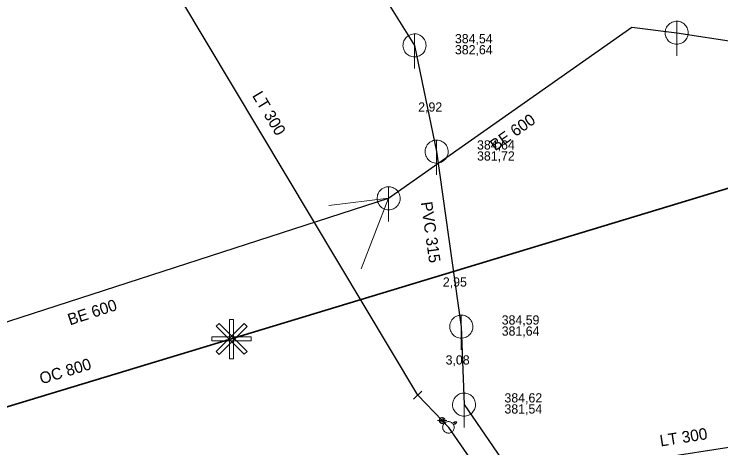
# Model space of a CAD drawing. Extents: x -809028 to -807737, y -990545 to -989489.
# Drawn here: x -808089.3 to -808027.9, y -989998.8 to -989961.2 of the extents above; entities that cross this region are included whole.
import ezdxf

# ---------------------------------------------------------------- set-up
doc = ezdxf.new("R2010")
doc.units = 0
doc.header["$LTSCALE"] = 0.32
for name, color, linetype, lineweight in [('1', 7, 'Continuous', 13), ('11', 7, 'Continuous', 13), ('12', 7, 'Continuous', 13), ('14', 7, 'Continuous', 25), ('17', 7, 'Continuous', 25), ('22', 7, 'Continuous', 13), ('23', 7, 'Continuous', 13), ('34', 7, 'Continuous', 13), ('9', 7, 'Continuous', 13)]:
    doc.layers.add(name, color=color, linetype=linetype, lineweight=lineweight)

msp = doc.modelspace()

# ---------------------------------------------------------------- linework, layer by layer
at = {"layer": '11'}
for p in [(-808061.958, -989977.796), (-808059.125, -989983.296)]:
    msp.add_line(p, (-808056.754, -989977.17), dxfattribs=at)
at = {"layer": '12'}
for points in [[(-808070.557, -989987.672), (-808070.206, -989987.672), (-808070.206, -989991.107), (-808070.557, -989991.107)], [(-808069.291, -989988.036), (-808069.043, -989988.284), (-808071.472, -989990.713), (-808071.718, -989990.465)], [(-808071.71, -989988.275), (-808071.463, -989988.027), (-808069.034, -989990.456), (-808069.281, -989990.704)], [(-808068.673, -989989.181), (-808068.673, -989989.531), (-808072.108, -989989.531), (-808072.108, -989989.181)]]:
    msp.add_lwpolyline(points, close=True, dxfattribs=at)
at = {"layer": '14'}
for p, q in [((-808068.949, -989940.649), (-808054.51, -989963.899)), ((-808031.76, -989962.8), (-808009.03, -989966.258)), ((-808054.51, -989963.899), (-808052.59, -989973.12)), ((-808052.59, -989973.12), (-808050.449, -989988.309)), ((-808107.581, -989993.61), (-808056.754, -989977.17)), ((-808050.449, -989988.309), (-808050.21, -989995.07)), ((-808050.21, -989995.07), (-808041.129, -990008.23))]:
    msp.add_line(p, q, dxfattribs=at)
at = {"layer": '14', "lineweight": 13}
for p, q in [((-808052.113, -989996.453), (-808054.229, -989994.256)), ((-808051.536, -989997.052), (-808052.113, -989996.453))]:
    msp.add_line(p, q, dxfattribs=at)
at = {"layer": '14'}
msp.add_lwpolyline([(-808056.754, -989977.17), (-808035.64, -989962.329), (-808031.76, -989962.8)], dxfattribs=at)
at = {"layer": '17'}
msp.add_line((-808054.229, -989994.256), (-808081.64, -989948.42), dxfattribs=at)
at = {"layer": '17', "lineweight": 35}
msp.add_lwpolyline([(-808175.378, -990021.169), (-807992.059, -989965.616), (-807931.655, -989894.969), (-807887.769, -989859.528)], dxfattribs=at)
at = {"layer": '17'}
msp.add_lwpolyline([(-808011.965, -989996.426), (-808048.094, -990002.026), (-808051.536, -989997.052)], dxfattribs=at)
at = {"layer": '22'}
for p, q in [((-808031.76, -989964.8), (-808031.759, -989961.8)), ((-808054.51, -989965.899), (-808054.509, -989962.899)), ((-808052.59, -989975.12), (-808052.589, -989972.12)), ((-808056.754, -989979.17), (-808056.753, -989976.17)), ((-808050.449, -989990.309), (-808050.448, -989987.309)), ((-808050.21, -989997.07), (-808050.209, -989994.07))]:
    msp.add_line(p, q, dxfattribs=at)
for points in [[(-808030.76, -989962.8), (-808030.765, -989962.691), (-808030.783, -989962.583), (-808030.813, -989962.477), (-808030.853, -989962.376), (-808030.905, -989962.279), (-808030.967, -989962.189), (-808031.039, -989962.106), (-808031.119, -989962.032), (-808031.207, -989961.966), (-808031.301, -989961.911), (-808031.401, -989961.866), (-808031.506, -989961.833), (-808031.613, -989961.811), (-808031.722, -989961.801), (-808031.832, -989961.803), (-808031.94, -989961.817), (-808032.047, -989961.842), (-808032.15, -989961.879), (-808032.248, -989961.928), (-808032.34, -989961.986), (-808032.426, -989962.055), (-808032.503, -989962.132), (-808032.572, -989962.218), (-808032.631, -989962.31), (-808032.679, -989962.408), (-808032.716, -989962.511), (-808032.742, -989962.618), (-808032.756, -989962.726), (-808032.759, -989962.836), (-808032.749, -989962.945), (-808032.728, -989963.052), (-808032.694, -989963.156), (-808032.65, -989963.256), (-808032.595, -989963.351), (-808032.529, -989963.439), (-808032.455, -989963.519), (-808032.372, -989963.591), (-808032.282, -989963.653), (-808032.186, -989963.705), (-808032.084, -989963.746), (-808031.979, -989963.776), (-808031.871, -989963.794), (-808031.761, -989963.8), (-808031.652, -989963.794), (-808031.544, -989963.776), (-808031.439, -989963.747), (-808031.337, -989963.706), (-808031.24, -989963.654), (-808031.15, -989963.592), (-808031.067, -989963.521), (-808030.992, -989963.441), (-808030.927, -989963.353), (-808030.871, -989963.259), (-808030.827, -989963.159), (-808030.793, -989963.055), (-808030.771, -989962.947), (-808030.761, -989962.838)], [(-808053.51, -989963.899), (-808053.515, -989963.79), (-808053.533, -989963.682), (-808053.563, -989963.576), (-808053.603, -989963.475), (-808053.655, -989963.378), (-808053.717, -989963.288), (-808053.789, -989963.205), (-808053.869, -989963.131), (-808053.957, -989963.065), (-808054.051, -989963.01), (-808054.151, -989962.965), (-808054.256, -989962.932), (-808054.363, -989962.91), (-808054.472, -989962.9), (-808054.582, -989962.902), (-808054.69, -989962.916), (-808054.797, -989962.941), (-808054.9, -989962.978), (-808054.998, -989963.027), (-808055.09, -989963.085), (-808055.176, -989963.154), (-808055.253, -989963.231), (-808055.322, -989963.317), (-808055.381, -989963.409), (-808055.429, -989963.507), (-808055.466, -989963.61), (-808055.492, -989963.717), (-808055.506, -989963.825), (-808055.509, -989963.935), (-808055.499, -989964.044), (-808055.478, -989964.151), (-808055.444, -989964.255), (-808055.4, -989964.355), (-808055.345, -989964.45), (-808055.279, -989964.538), (-808055.205, -989964.618), (-808055.122, -989964.69), (-808055.032, -989964.752), (-808054.936, -989964.804), (-808054.834, -989964.845), (-808054.729, -989964.875), (-808054.621, -989964.893), (-808054.511, -989964.899), (-808054.402, -989964.893), (-808054.294, -989964.875), (-808054.189, -989964.846), (-808054.087, -989964.805), (-808053.99, -989964.753), (-808053.9, -989964.691), (-808053.817, -989964.62), (-808053.742, -989964.54), (-808053.677, -989964.452), (-808053.621, -989964.358), (-808053.577, -989964.258), (-808053.543, -989964.154), (-808053.521, -989964.046), (-808053.511, -989963.937)], [(-808051.59, -989973.12), (-808051.595, -989973.011), (-808051.613, -989972.903), (-808051.643, -989972.797), (-808051.683, -989972.696), (-808051.735, -989972.599), (-808051.797, -989972.509), (-808051.869, -989972.426), (-808051.949, -989972.352), (-808052.037, -989972.286), (-808052.131, -989972.231), (-808052.231, -989972.186), (-808052.336, -989972.153), (-808052.443, -989972.131), (-808052.552, -989972.121), (-808052.662, -989972.123), (-808052.77, -989972.137), (-808052.877, -989972.162), (-808052.98, -989972.199), (-808053.078, -989972.248), (-808053.17, -989972.306), (-808053.256, -989972.375), (-808053.333, -989972.452), (-808053.402, -989972.538), (-808053.461, -989972.63), (-808053.509, -989972.728), (-808053.546, -989972.831), (-808053.572, -989972.938), (-808053.586, -989973.046), (-808053.589, -989973.156), (-808053.579, -989973.265), (-808053.558, -989973.372), (-808053.524, -989973.476), (-808053.48, -989973.576), (-808053.425, -989973.671), (-808053.359, -989973.759), (-808053.285, -989973.839), (-808053.202, -989973.911), (-808053.112, -989973.973), (-808053.016, -989974.025), (-808052.914, -989974.066), (-808052.809, -989974.096), (-808052.701, -989974.114), (-808052.591, -989974.12), (-808052.482, -989974.114), (-808052.374, -989974.096), (-808052.269, -989974.067), (-808052.167, -989974.026), (-808052.07, -989973.974), (-808051.98, -989973.912), (-808051.897, -989973.841), (-808051.822, -989973.761), (-808051.757, -989973.673), (-808051.701, -989973.579), (-808051.657, -989973.479), (-808051.623, -989973.375), (-808051.601, -989973.267), (-808051.591, -989973.158)], [(-808055.754, -989977.17), (-808055.759, -989977.061), (-808055.777, -989976.953), (-808055.807, -989976.847), (-808055.847, -989976.746), (-808055.899, -989976.649), (-808055.961, -989976.559), (-808056.033, -989976.476), (-808056.113, -989976.402), (-808056.201, -989976.336), (-808056.295, -989976.281), (-808056.395, -989976.236), (-808056.5, -989976.203), (-808056.607, -989976.181), (-808056.716, -989976.171), (-808056.826, -989976.173), (-808056.934, -989976.187), (-808057.041, -989976.212), (-808057.144, -989976.249), (-808057.242, -989976.298), (-808057.334, -989976.356), (-808057.42, -989976.425), (-808057.497, -989976.502), (-808057.566, -989976.588), (-808057.625, -989976.68), (-808057.673, -989976.778), (-808057.71, -989976.881), (-808057.736, -989976.988), (-808057.75, -989977.096), (-808057.753, -989977.206), (-808057.743, -989977.315), (-808057.722, -989977.422), (-808057.688, -989977.526), (-808057.644, -989977.626), (-808057.589, -989977.721), (-808057.523, -989977.809), (-808057.449, -989977.889), (-808057.366, -989977.961), (-808057.276, -989978.023), (-808057.18, -989978.075), (-808057.078, -989978.116), (-808056.973, -989978.146), (-808056.865, -989978.164), (-808056.755, -989978.17), (-808056.646, -989978.164), (-808056.538, -989978.146), (-808056.433, -989978.117), (-808056.331, -989978.076), (-808056.234, -989978.024), (-808056.144, -989977.962), (-808056.061, -989977.891), (-808055.986, -989977.811), (-808055.921, -989977.723), (-808055.865, -989977.629), (-808055.821, -989977.529), (-808055.787, -989977.425), (-808055.765, -989977.317), (-808055.755, -989977.208)], [(-808049.449, -989988.309), (-808049.454, -989988.2), (-808049.472, -989988.092), (-808049.502, -989987.986), (-808049.542, -989987.885), (-808049.594, -989987.788), (-808049.656, -989987.698), (-808049.728, -989987.615), (-808049.808, -989987.541), (-808049.896, -989987.475), (-808049.99, -989987.42), (-808050.09, -989987.375), (-808050.195, -989987.342), (-808050.302, -989987.32), (-808050.411, -989987.31), (-808050.521, -989987.312), (-808050.629, -989987.326), (-808050.736, -989987.351), (-808050.839, -989987.388), (-808050.937, -989987.437), (-808051.029, -989987.495), (-808051.115, -989987.564), (-808051.192, -989987.641), (-808051.261, -989987.727), (-808051.32, -989987.819), (-808051.368, -989987.917), (-808051.405, -989988.02), (-808051.431, -989988.127), (-808051.445, -989988.235), (-808051.448, -989988.345), (-808051.438, -989988.454), (-808051.417, -989988.561), (-808051.383, -989988.665), (-808051.339, -989988.765), (-808051.284, -989988.86), (-808051.218, -989988.948), (-808051.144, -989989.028), (-808051.061, -989989.1), (-808050.971, -989989.162), (-808050.875, -989989.214), (-808050.773, -989989.255), (-808050.668, -989989.285), (-808050.56, -989989.303), (-808050.45, -989989.309), (-808050.341, -989989.303), (-808050.233, -989989.285), (-808050.128, -989989.256), (-808050.026, -989989.215), (-808049.929, -989989.163), (-808049.839, -989989.101), (-808049.756, -989989.03), (-808049.681, -989988.95), (-808049.616, -989988.862), (-808049.56, -989988.768), (-808049.516, -989988.668), (-808049.482, -989988.564), (-808049.46, -989988.456), (-808049.45, -989988.347)], [(-808049.21, -989995.07), (-808049.215, -989994.961), (-808049.233, -989994.853), (-808049.263, -989994.747), (-808049.303, -989994.646), (-808049.355, -989994.549), (-808049.417, -989994.459), (-808049.489, -989994.376), (-808049.569, -989994.302), (-808049.657, -989994.236), (-808049.751, -989994.181), (-808049.851, -989994.136), (-808049.956, -989994.103), (-808050.063, -989994.081), (-808050.172, -989994.071), (-808050.282, -989994.073), (-808050.39, -989994.087), (-808050.497, -989994.112), (-808050.6, -989994.149), (-808050.698, -989994.198), (-808050.79, -989994.256), (-808050.876, -989994.325), (-808050.953, -989994.402), (-808051.022, -989994.488), (-808051.081, -989994.58), (-808051.129, -989994.678), (-808051.166, -989994.781), (-808051.192, -989994.888), (-808051.206, -989994.996), (-808051.209, -989995.106), (-808051.199, -989995.215), (-808051.178, -989995.322), (-808051.144, -989995.426), (-808051.1, -989995.526), (-808051.045, -989995.621), (-808050.979, -989995.709), (-808050.905, -989995.789), (-808050.822, -989995.861), (-808050.732, -989995.923), (-808050.636, -989995.975), (-808050.534, -989996.016), (-808050.429, -989996.046), (-808050.321, -989996.064), (-808050.211, -989996.07), (-808050.102, -989996.064), (-808049.994, -989996.046), (-808049.889, -989996.017), (-808049.787, -989995.976), (-808049.69, -989995.924), (-808049.6, -989995.862), (-808049.517, -989995.791), (-808049.442, -989995.711), (-808049.377, -989995.623), (-808049.321, -989995.529), (-808049.277, -989995.429), (-808049.243, -989995.325), (-808049.221, -989995.217), (-808049.211, -989995.108)]]:
    msp.add_lwpolyline(points, close=True, dxfattribs=at)
at = {"layer": '23'}
msp.add_line((-808050.954, -989996.754), (-808051.066, -989996.592), dxfattribs=at)
for points in [[(-808051.278, -989997.454), (-808051.237, -989997.421), (-808051.199, -989997.384), (-808051.167, -989997.344), (-808051.138, -989997.3), (-808051.113, -989997.254), (-808051.094, -989997.205), (-808051.08, -989997.155), (-808051.072, -989997.104), (-808051.068, -989997.051), (-808051.07, -989996.999), (-808051.077, -989996.947), (-808051.091, -989996.896), (-808051.108, -989996.847), (-808051.132, -989996.801), (-808051.159, -989996.757), (-808051.193, -989996.715), (-808051.228, -989996.678), (-808051.27, -989996.644), (-808051.311, -989996.615), (-808051.358, -989996.59), (-808051.408, -989996.572), (-808051.458, -989996.558), (-808051.511, -989996.549), (-808051.562, -989996.545), (-808051.614, -989996.547), (-808051.666, -989996.556), (-808051.716, -989996.568), (-808051.765, -989996.587), (-808051.812, -989996.611), (-808051.857, -989996.638), (-808051.898, -989996.67), (-808051.935, -989996.707), (-808051.969, -989996.747), (-808051.998, -989996.79), (-808052.021, -989996.836), (-808052.04, -989996.885), (-808052.055, -989996.936), (-808052.064, -989996.988), (-808052.067, -989997.04)], [(-808051.27, -989996.644), (-808051.311, -989996.615), (-808051.358, -989996.59), (-808051.408, -989996.572), (-808051.458, -989996.558), (-808051.511, -989996.549), (-808051.562, -989996.545), (-808051.614, -989996.547), (-808051.666, -989996.556), (-808051.716, -989996.568), (-808051.765, -989996.587), (-808051.812, -989996.611), (-808051.857, -989996.638), (-808051.898, -989996.67), (-808051.935, -989996.707), (-808051.969, -989996.747), (-808051.998, -989996.79), (-808052.021, -989996.836), (-808052.04, -989996.885), (-808052.055, -989996.936), (-808052.064, -989996.988), (-808052.067, -989997.04), (-808052.066, -989997.091), (-808052.057, -989997.144), (-808052.045, -989997.194), (-808052.026, -989997.244), (-808052.002, -989997.29), (-808051.975, -989997.334), (-808051.942, -989997.375), (-808051.906, -989997.413), (-808051.866, -989997.447), (-808051.822, -989997.475), (-808051.775, -989997.5), (-808051.728, -989997.519), (-808051.676, -989997.532), (-808051.626, -989997.542), (-808051.574, -989997.545), (-808051.52, -989997.543), (-808051.469, -989997.535), (-808051.418, -989997.522)], [(-808052.067, -989997.04), (-808052.066, -989997.091), (-808052.057, -989997.144), (-808052.045, -989997.194), (-808052.026, -989997.244), (-808052.002, -989997.29), (-808051.975, -989997.334), (-808051.942, -989997.375), (-808051.906, -989997.413), (-808051.866, -989997.447), (-808051.822, -989997.475), (-808051.775, -989997.5), (-808051.728, -989997.519), (-808051.676, -989997.532), (-808051.626, -989997.542), (-808051.574, -989997.545), (-808051.52, -989997.543), (-808051.469, -989997.535), (-808051.418, -989997.522), (-808051.369, -989997.503), (-808051.323, -989997.481), (-808051.278, -989997.454), (-808051.237, -989997.421), (-808051.199, -989997.384), (-808051.167, -989997.344), (-808051.138, -989997.3), (-808051.113, -989997.254), (-808051.094, -989997.205), (-808051.08, -989997.155), (-808051.072, -989997.104), (-808051.068, -989997.051), (-808051.07, -989996.999), (-808051.077, -989996.947), (-808051.091, -989996.896), (-808051.108, -989996.847), (-808051.132, -989996.801), (-808051.159, -989996.757), (-808051.193, -989996.715), (-808051.228, -989996.678), (-808051.27, -989996.644)], [(-808051.146, -989996.648), (-808051.023, -989996.563), (-808050.842, -989996.558), (-808050.911, -989996.724), (-808051.034, -989996.809)], [(-808051.418, -989997.522), (-808051.369, -989997.503), (-808051.323, -989997.481), (-808051.278, -989997.454)]]:
    msp.add_lwpolyline(points, dxfattribs=at)
at = {"layer": '34'}
msp.add_line((-808053.863, -989993.915), (-808054.595, -989994.596), dxfattribs=at)
at = {"layer": '9'}
msp.add_line((-808052.524, -989996.445), (-808051.701, -989996.46), dxfattribs=at)
for points in [[(-808052.287, -989996.273), (-808052.305, -989996.29), (-808052.321, -989996.311), (-808052.333, -989996.334), (-808052.345, -989996.359), (-808052.353, -989996.385), (-808052.358, -989996.409), (-808052.362, -989996.434), (-808052.363, -989996.461), (-808052.36, -989996.487), (-808052.355, -989996.512), (-808052.347, -989996.538), (-808052.338, -989996.562), (-808052.325, -989996.584), (-808052.31, -989996.606), (-808052.292, -989996.626), (-808052.274, -989996.644), (-808052.253, -989996.66), (-808052.231, -989996.673), (-808052.206, -989996.684), (-808052.181, -989996.693), (-808052.156, -989996.697), (-808052.132, -989996.701), (-808052.103, -989996.703), (-808052.077, -989996.7), (-808052.052, -989996.696), (-808052.028, -989996.687), (-808052.002, -989996.676), (-808051.981, -989996.665), (-808051.958, -989996.65), (-808051.939, -989996.633), (-808051.921, -989996.613), (-808051.905, -989996.593), (-808051.891, -989996.57), (-808051.88, -989996.546), (-808051.872, -989996.521), (-808051.867, -989996.496), (-808051.864, -989996.47), (-808051.864, -989996.443), (-808051.865, -989996.416), (-808051.871, -989996.391), (-808051.877, -989996.368), (-808051.887, -989996.343), (-808051.899, -989996.32), (-808051.915, -989996.297), (-808051.933, -989996.278), (-808051.951, -989996.26), (-808051.972, -989996.245), (-808051.994, -989996.231), (-808052.019, -989996.221), (-808052.043, -989996.212), (-808052.069, -989996.205), (-808052.095, -989996.203), (-808052.122, -989996.202), (-808052.149, -989996.205), (-808052.173, -989996.211), (-808052.198, -989996.217), (-808052.221, -989996.227), (-808052.245, -989996.24), (-808052.267, -989996.255)], [(-808052.192, -989996.569), (-808052.165, -989996.573), (-808052.126, -989996.58), (-808052.103, -989996.57), (-808052.065, -989996.553), (-808052.015, -989996.505), (-808051.995, -989996.466), (-808051.985, -989996.445), (-808051.99, -989996.404), (-808051.993, -989996.377), (-808052.034, -989996.336), (-808052.06, -989996.33), (-808052.097, -989996.327), (-808052.123, -989996.335), (-808052.161, -989996.353), (-808052.212, -989996.4), (-808052.23, -989996.439), (-808052.238, -989996.464), (-808052.235, -989996.501), (-808052.231, -989996.528)], [(-808052.524, -989996.445), (-808052.4, -989996.477), (-808052.399, -989996.416)]]:
    msp.add_lwpolyline(points, close=True, dxfattribs=at)

# ---------------------------------------------------------------- texts
at = {"layer": '1'}
for s, rotation, p in [('LT 300', 301, (-808068.628, -989968.256)), ('BE 600', 35, (-808047.509, -989973.099)), ('PVC 315 ', 278, (-808053.973, -989977.525)), ('BE 600', 18, (-808084.41, -989988.201)), ('OC 800', 17, (-808086.875, -989993.319)), ('LT 300', 9, (-808033.145, -989998.711))]:
    msp.add_text(s, height=1, rotation=rotation, dxfattribs=at).set_placement(p)
for s, p in [('2,92', (-808054.19, -989969.644)), ('2,95', (-808052.049, -989984.834)), ('3,08', (-808051.81, -989991.594))]:
    msp.add_text(s, height=0.8, dxfattribs=at).set_placement(p)
at = {"layer": '14'}
for s, p in [('384,54', (-808051.003, -989963.716)), ('382,64', (-808051.003, -989964.676)), ('384,64', (-808049.083, -989972.936)), ('381,72', (-808049.083, -989973.896)), ('384,59', (-808046.943, -989988.126)), ('381,64', (-808046.943, -989989.086)), ('384,62', (-808046.703, -989994.886)), ('381,54', (-808046.703, -989995.846))]:
    msp.add_text(s, height=0.8, dxfattribs=at).set_placement(p)

doc.saveas('drawing.dxf')
